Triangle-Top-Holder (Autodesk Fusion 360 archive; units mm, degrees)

design "Triangle-Top-Holder" references "Base"
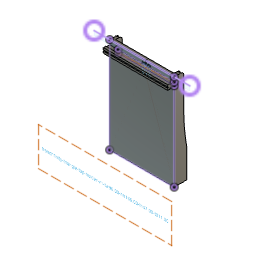
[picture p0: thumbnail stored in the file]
parameter "tool_width" = 96
parameter "holder_height" = 155
parameter "triangle_height" = 47
parameter "tolerance" = 1
parameter "wall_thickness" = 5
parameter "tool_depth" = 11
sketch "Base" plane through (0, 0, 0) normal (0, 1, 0) x axis (1, 0, 0)
  line L1 (108, 0) -> (0, 0)
  line L2 (108, -160) -> (108, 0)
  line L3 (0, -160) -> (108, -160)
  line L4 (0, 0) -> (0, -160)
  line L5 (54, -48) -> (54, 0)
  line L6 (108, -48) -> (54, -48)
  line L7 (103, -155) -> (103, -5)
  line L8 (5, -155) -> (103, -155)
  line L9 (5, -5) -> (5, -155)
  line L10 (103, -5) -> (5, -5)
  line L11 (54, -5) -> (103, -48)
  line L12 (54, -5) -> (5, -48)
  line L13 (103, -160) -> (103, -155)
  line L14 (5, -160) -> (5, -155)
  point P1 (0, 0)
  point P2 (0, 0)
  point P6 (54, 0)
  point P8 (108, -48)
  point P13 (103, -48)
  point P14 (54, -5)
  point P15 (5, -48)
  point P16 (54, -5)
  point P17 (103, -160)
  point P10 (103, -155)
  point P18 (5, -155)
  point P19 (5, -160)
  point P3 (108, 0)
  point P5 (0, -160)
  point P7 (54, -48)
  horizontal L1
  vertical L2
  horizontal L3
  vertical L4
  coincident P1 P2
  midpoint L1 P6
  perpendicular L1 L5
  coincident L2 P8
  perpendicular L2 L6
  coincident L6 P13
  coincident L7 P13
  midpoint L10 P14
  symmetric L5 P13 P15
  symmetric L5 P14 P16
  coincident L3 P17
  perpendicular L3 L13
  symmetric L5 P10 P18
  symmetric L5 P17 P19
  dimension "d7" distance P2 P3 = 108 (= "wall_thickness + wall_thickness + tolerance + tolerance + tool_width")
  dimension "d8" distance P2 P5 = 160 (= "holder_height + wall_thickness")
  dimension "d9" distance P6 P7 = 48 (= "triangle_height + tolerance")
  dimension "d10" = 5 (= "wall_thickness")
extrude "Extrude1" new body sketch "Base" profile of L1 L2 L3 L4 L10 L9 L8 L7 L11 L12 along normal blind 5 (= "wall_thickness") bodies "Holder"
extrude "Extrude2" add sketch "Base" profile of L1 L2 L3 L4 L10 L9 L7 L11 L12 L13 L14 against normal blind 11 (magnitude of "tool_depth * -1")
sketch "Cover" plane through (0, -11, 0) normal (0, -1, 0) x axis (1, 0, 0)
  line L1 (5, 48) -> (54, 5)
  line L2 (5, 160) -> (5, 48)
  line L3 (0, 160) -> (5, 160)
  line L4 (0, 0) -> (0, 160)
  line L5 (108, 0) -> (0, 0)
  line L6 (108, 160) -> (108, 0)
  line L7 (103, 160) -> (108, 160)
  line L8 (103, 48) -> (103, 160)
  line L9 (54, 5) -> (103, 48)
  line L10 (108, 0) -> (0, 0)
  line L11 (108, 48) -> (108, 0)
  line L12 (0, 48) -> (108, 48)
  line L13 (0, 0) -> (0, 48)
  point P7 (108, 0)
  point P12 (108, 0)
  point P6 (0, 0)
  point P11 (0, 0)
  point P14 (0, 48)
  perpendicular L10 L11
  parallel L10 L12
  parallel L11 L13
  coincident P7 P12
  perpendicular L6 L10
  coincident P6 P11
  dimension "d17" distance P11 P14 = 48 (= "triangle_height + tolerance")
extrude "Extrude3" add sketch "Cover" profile of L1 L2 L4 L5 L6 L8 L9 L10 L11 L12 L13 along normal blind 5 (= "wall_thickness")
fillet "Fillet2" radius 310 (= "holder_height * 2")
fillet "Fillet3" radius 2 5 (= "wall_thickness")
fillet "Fillet4" radius 5
component_insert "Component Insert"
sketch "Reference" plane through (0, 55.6118, 0) normal (0, 1, 0) x axis (-1, 0, 0)
  line L1 (0, 52.6059) -> (-160, 52.6059)
  line L2 (0, 60) -> (0, 52.6059)
  line L3 (-160, 60) -> (0, 60)
  line L4 (-160, 52.6059) -> (-160, 60)
  line L5 (-160, 60) -> (0, 60)
move "Move1"
move "Move2"
extrude "Extrude5" add of existing geometry to an object
extrude "Extrude6" cut of existing geometry to an object
sketch "Text" plane through (0, 55.6118, 0) normal (0, -1, 0) x axis (1, 0, 0)
  line L1 (40, 47.1259) -> (134, 47.1259)
  line L2 (26, -100) -> (26, 60)
  line L3 (134, -100) -> (26, -100)
  line L4 (134, 60) -> (134, 52.4859)
  curve K1
  curve K2
  curve K3
  curve K4
  line L5 (40, 52.4859) -> (40, 47.1259)
  line L6 (134, 52.4859) -> (40, 52.4859)
  line L7 (26, 60) -> (134, 60)
  line L8 (134, 47.1259) -> (134, -100)
  point P5 (134, 52.4859)
  point P3 (40, 47.1259)
  coincident P5
  coincident P3
  dimension "d34" Text1-Height = 3
extrude "Extrude7" cut sketch "Text" against normal blind 2
sketch "Filename" plane through (0, 0, 0) normal (0, 1, 0) x axis (1, 0, 0)
  dimension "d37" = 5
extrude "Extrude8" add of existing geometry to an object
named bodies: "Holder"

design "Base"
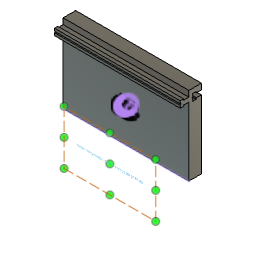
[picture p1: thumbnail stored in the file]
parameter "wall_anchor_height" = 60
parameter "wall_anchor_width" = 20
parameter "wall_anchor_angle" = 45
parameter "width_per_slot" = 40
parameter "slot_inner_width" = 8.5
parameter "slot_inner_height" = 4.5
parameter "slot_outer_width" = 5.6
parameter "slot_outer_height" = 6.5
parameter "slot_dept" = 15
parameter "print_tolerance" = 0.12
parameter "base_plate_thickness" = 16
parameter "base_plate_slot_height" = 50
parameter "wall_anchor_angle_rounded_border" = 1.5
parameter "base_plate_screw_hole_diameter" = 4
parameter "base_plate_screw_head_diameter" = 8
parameter "base_plate_screw_head_height" = 4
parameter "base_plate_screw_hole_side_distance" = 7
parameter "slot_screw_head_width" = 4.42 (= "4.3 mm + print_tolerance")
parameter "slot_screw_thread_width" = 2.12 (= "2 mm + print_tolerance")
parameter "slot_screw_head_height" = 2.12 (= "2 mm + print_tolerance")
parameter "width" = 160
parameter "filament_hole_width" = 1.7
parameter "plate_height" = 80
sketch "Side" plane through (0, 0, 0) normal (1, 0, 0) x axis (0, 1, 0)
  line L1 (39.6118, 0) -> (19.6118, 0)
  line L2 (39.6118, 60) -> (39.6118, 0)
  line L3 (19.6118, 60) -> (39.6118, 60)
  line L4 (19.6118, 0) -> (19.6118, 60)
  line L5 (39.6118, 39.6118) -> (0, 0)
  line L6 (56.0196, 0) -> (0, 0)
  point P1 (0, 0)
  point P6 (0, 0)
  point P7 (39.6118, 39.6118)
  point P2 (19.6118, 0)
  point P3 (39.6118, 0)
  point P5 (19.6118, 60)
  horizontal L1
  vertical L2
  horizontal L3
  vertical L4
  horizontal L6
  coincident P1 P6
  coincident L2 P7
  dimension "d4" distance P2 P3 = 20 (= "wall_anchor_width")
  dimension "d5" distance P2 P5 = 60 (= "wall_anchor_height")
  dimension "d6" angle L5 L6 = 45 (= "wall_anchor_angle")
extrude "Extrude1" new body sketch "Side" profile of L1 L2 L3 L4 L5 along normal blind 40 (= "width_per_slot")
sketch "Slot LeftToRight" plane through (0, 0, 0) normal (-1, 0, 0) x axis (0, -1, 0)
  line L1 (-19.6118, 60) -> (-19.6118, 19.6118)
  line L2 (-39.6118, 60) -> (-19.6118, 60)
  line L3 (-39.6118, 39.6118) -> (-39.6118, 60)
  line L4 (-19.6118, 19.6118) -> (-39.6118, 39.6118)
  line L5 (-39.6118, 52.6059) -> (-39.6118, 49.8059)
  line L6 (-39.6118, 47.0059) -> (-39.6118, 49.8059)
  line L7 (-33.1118, 52.6059) -> (-39.6118, 52.6059)
  line L8 (-28.6118, 49.8059) -> (-39.6118, 49.8059)
  line L9 (-28.6118, 54.0559) -> (-28.6118, 49.8059)
  line L10 (-33.1118, 54.0559) -> (-28.6118, 54.0559)
  line L11 (-33.1118, 52.6059) -> (-33.1118, 54.0559)
  line L12 (-28.6118, 45.5559) -> (-28.6118, 49.8059)
  line L13 (-33.1118, 45.5559) -> (-28.6118, 45.5559)
  line L14 (-33.1118, 47.0059) -> (-33.1118, 45.5559)
  line L15 (-33.1118, 47.0059) -> (-39.6118, 47.0059)
  point P6 (-39.6118, 49.8059)
  point P7 (-39.6118, 52.6059)
  point P17 (-39.6118, 47.0059)
  point P9 (-33.1118, 52.6059)
  point P16 (-33.1118, 47.0059)
  point P10 (-28.6118, 49.8059)
  point P13 (-28.6118, 49.8059)
  point P11 (-28.6118, 54.0559)
  point P14 (-28.6118, 45.5559)
  point P12 (-33.1118, 54.0559)
  point P15 (-33.1118, 45.5559)
  midpoint L3 P6
  parallel L3 L5
  parallel L3 L6
  perpendicular L3 L7
  perpendicular L6 L8
  perpendicular L8 L9
  perpendicular L9 L10
  symmetric P7 L8 P17
  symmetric P9 L8 P16
  symmetric P10 L8 P13
  symmetric L8 P11 P14
  symmetric L8 P12 P15
  dimension "d80" distance P6 P7 = 2.8 (= "slot_outer_width / 2")
  dimension "d82" distance P7 P9 = 6.5 (= "slot_outer_height")
  dimension "d84" distance P6 P10 = 11 (= "slot_outer_height + slot_inner_height")
  dimension "d85" distance P10 P11 = 4.25 (= "slot_inner_width / 2")
  dimension "d86" distance P11 P12 = 4.5 (= "slot_inner_height")
extrude "Extrude3" cut sketch "Slot LeftToRight" profile of L3 L5 L6 L7 L9 L10 L11 L12 L13 L14 L15 against normal blind 40 (magnitude of "width_per_slot * -1")
sketch "Plate" plane through (0, 39.6118, 0) normal (0, 1, 0) x axis (-1, 0, 0)
  line L1 (0, 39.6118) -> (-40, 39.6118)
  line L2 (-40, 60) -> (0, 60)
  line L3 (0, 10) -> (0, 60)
  line L4 (-40, 10) -> (-40, 60)
  line L5 (-40, 10) -> (0, 10)
  line L6 (-40, 47.0059) -> (0, 47.0059)
  line L7 (-40, 52.6059) -> (-40, 60)
  line L8 (0, 60) -> (0, 52.6059)
  line L9 (0, 52.6059) -> (-40, 52.6059)
  line L10 (-40, 60) -> (0, 60)
  line L11 (-40, 39.6118) -> (-40, 47.0059)
  line L12 (0, 47.0059) -> (0, 39.6118)
  point P2 (0, 60)
  point P3 (-40, 60)
  point P4 (0, 10)
  point P5 (-40, 10)
  perpendicular L1 L3
  perpendicular L1 L4
  dimension "d36" distance P2 P3 = 40 (= "width_per_slot")
  dimension "d37" distance P2 P4 = 50 (= "base_plate_slot_height")
  dimension "d39" distance P3 P5 = 50 (= "base_plate_slot_height")
extrude "Extrude6" new body sketch "Plate" profile of L1 L2 L3 L4 L5 L6 L7 L8 L9 L10 along normal blind 16 (= "base_plate_thickness") bodies "Base plate with slot"
sketch "Slot" plane through (0, 0, 0) normal (-1, 0, 0) x axis (0, -1, 0)
  line L1 (-19.6118, 60) -> (-19.6118, 19.6118)
  line L2 (-39.6118, 60) -> (-19.6118, 60)
  line L3 (-39.6118, 52.6059) -> (-39.6118, 60)
  line L4 (-33.1118, 52.6059) -> (-39.6118, 52.6059)
  line L5 (-33.1118, 54.0559) -> (-33.1118, 52.6059)
  line L6 (-28.6118, 54.0559) -> (-33.1118, 54.0559)
  line L7 (-28.6118, 45.5559) -> (-28.6118, 54.0559)
  line L8 (-33.1118, 45.5559) -> (-28.6118, 45.5559)
  line L9 (-33.1118, 47.0059) -> (-33.1118, 45.5559)
  line L10 (-39.6118, 47.0059) -> (-33.1118, 47.0059)
  line L11 (-39.6118, 39.6118) -> (-39.6118, 47.0059)
  line L12 (-19.6118, 19.6118) -> (-39.6118, 39.6118)
  line L13 (-33.1118, 52.6059) -> (-39.6118, 52.6059)
  line L14 (-33.1118, 54.0559) -> (-33.1118, 52.6059)
  line L15 (-28.6118, 54.0559) -> (-33.1118, 54.0559)
  line L16 (-28.6118, 45.5559) -> (-28.6118, 54.0559)
  line L17 (-33.1118, 45.5559) -> (-28.6118, 45.5559)
  line L18 (-33.1118, 47.0059) -> (-33.1118, 45.5559)
  line L19 (-39.6118, 47.0059) -> (-33.1118, 47.0059)
  line L20 (-39.6118, 10) -> (-39.6118, 60)
  line L21 (-32.9918, 52.4859) -> (-39.6118, 52.4859)
  line L22 (-32.9918, 53.9359) -> (-32.9918, 52.4859)
  line L23 (-28.7318, 53.9359) -> (-32.9918, 53.9359)
  line L24 (-28.7318, 45.6759) -> (-28.7318, 53.9359)
  line L25 (-32.9918, 45.6759) -> (-28.7318, 45.6759)
  line L26 (-32.9918, 47.1259) -> (-32.9918, 45.6759)
  line L27 (-39.6118, 47.1259) -> (-32.9918, 47.1259)
  line L28 (-33.1118, 52.6059) -> (-39.6118, 52.6059)
  line L29 (-33.1118, 52.6059) -> (-33.1118, 54.0559)
  line L30 (-28.6118, 54.0559) -> (-33.1118, 54.0559)
  line L31 (-28.6118, 45.5559) -> (-28.6118, 54.0559)
  line L32 (-33.1118, 45.5559) -> (-28.6118, 45.5559)
  line L33 (-33.1118, 47.0059) -> (-33.1118, 45.5559)
  line L34 (-39.6118, 47.0059) -> (-33.1118, 47.0059)
  line L35 (-39.6118, 47.0059) -> (-39.6118, 52.6059)
  line L36 (-49.1118, 52.6059) -> (-55.6118, 52.6059)
  line L37 (-49.1118, 52.6059) -> (-49.1118, 54.0559)
  line L38 (-44.6118, 54.0559) -> (-49.1118, 54.0559)
  line L39 (-44.6118, 45.5559) -> (-44.6118, 54.0559)
  line L40 (-49.1118, 45.5559) -> (-44.6118, 45.5559)
  line L41 (-49.1118, 47.0059) -> (-49.1118, 45.5559)
  line L42 (-55.6118, 47.0059) -> (-49.1118, 47.0059)
  line L43 (-55.6118, 47.0059) -> (-55.6118, 52.6059)
  point P15 (-39.6118, 52.6059)
  point P33 (-39.6118, 52.6059)
  point P16 (-33.1118, 52.6059)
  point P34 (-33.1118, 52.6059)
  point P17 (-33.1118, 54.0559)
  point P35 (-33.1118, 54.0559)
  point P36 (-33.1118, 52.6059)
  point P18 (-28.6118, 54.0559)
  point P37 (-28.6118, 54.0559)
  point P19 (-28.6118, 45.5559)
  point P38 (-28.6118, 45.5559)
  point P10 (-28.6118, 45.5559)
  point P39 (-28.6118, 45.5559)
  point P11 (-33.1118, 45.5559)
  point P40 (-33.1118, 45.5559)
  point P41 (-33.1118, 45.5559)
  point P12 (-33.1118, 47.0059)
  point P42 (-33.1118, 47.0059)
  point P21 (-33.1118, 47.0059)
  point P43 (-33.1118, 47.0059)
  point P22 (-39.6118, 47.0059)
  point P44 (-39.6118, 47.0059)
  point P45 (-39.6118, 52.6059)
  point P46 (-39.6118, 47.0059)
  coincident P15 P33
  coincident P16 P34
  coincident P17 P35
  coincident P16 P36
  coincident P18 P37
  coincident P19 P38
  coincident P10 P39
  coincident P11 P40
  coincident P11 P41
  coincident P12 P42
  coincident P21 P43
  coincident P22 P44
  coincident P15 P45
  coincident P22 P46
  dimension "d91" = 0.12 (= "print_tolerance")
  dimension "d96" R-Pattern1-uDistance = -16 (= "base_plate_thickness * -1")
  dimension "d97" R-Pattern1-vDistance = 0
extrude "Extrude7" add sketch "Slot" profile of L20 L24 L23 L27 L22 L25 L26 L21 against normal blind 40 (magnitude of "width_per_slot * -1")
extrude "Extrude8" cut sketch "Slot" profile of L36 L37 L38 L39 L40 L41 L42 L43 no distance stored
sketch "Sketch3" plane through (0, 0, 0) normal (-1, 0, 0) x axis (0, -1, 0)
  line L1 (-32.9918, 47.1259) -> (-39.6118, 47.1259)
  line L2 (-32.9918, 45.6759) -> (-32.9918, 47.1259)
  line L3 (-28.7318, 45.6759) -> (-32.9918, 45.6759)
  line L4 (-28.7318, 53.9359) -> (-28.7318, 45.6759)
  line L5 (-32.9918, 53.9359) -> (-28.7318, 53.9359)
  line L6 (-32.9918, 52.4859) -> (-32.9918, 53.9359)
  line L7 (-39.6118, 52.4859) -> (-32.9918, 52.4859)
  line L8 (-44.6118, 45.5559) -> (-44.6118, 54.0559)
  line L9 (-32.9918, 52.4859) -> (-39.6118, 52.4859)
  line L10 (-32.9918, 53.9359) -> (-32.9918, 52.4859)
  line L11 (-28.7318, 53.9359) -> (-32.9918, 53.9359)
  line L12 (-28.7318, 45.6759) -> (-28.7318, 53.9359)
  line L13 (-32.9918, 45.6759) -> (-28.7318, 45.6759)
  line L14 (-32.9918, 47.1259) -> (-32.9918, 45.6759)
  line L15 (-39.6118, 47.1259) -> (-32.9918, 47.1259)
  line L16 (-39.6118, 47.1259) -> (-39.6118, 52.4859)
  line L17 (-55.6118, 52.4859) -> (-48.9918, 52.4859)
  line L18 (-48.9918, 52.4859) -> (-48.9918, 53.9359)
  line L19 (-48.9918, 53.9359) -> (-44.7318, 53.9359)
  line L20 (-44.7318, 45.6759) -> (-44.7318, 53.9359)
  line L21 (-48.9918, 45.6759) -> (-44.7318, 45.6759)
  line L22 (-48.9918, 47.1259) -> (-48.9918, 45.6759)
  line L23 (-55.6118, 47.1259) -> (-48.9918, 47.1259)
  line L24 (-55.6118, 47.1259) -> (-55.6118, 52.4859)
  line L25 (-55.6118, 47.0059) -> (-49.1118, 47.0059)
  line L26 (-55.6118, 10) -> (-55.6118, 47.0059)
  line L27 (-39.6118, 10) -> (-55.6118, 10)
  line L28 (-39.6118, 47.1259) -> (-39.6118, 10)
  line L29 (-39.6118, 60) -> (-39.6118, 52.4859)
  line L30 (-55.6118, 60) -> (-39.6118, 60)
  line L31 (-55.6118, 52.6059) -> (-55.6118, 60)
  line L32 (-49.1118, 52.6059) -> (-55.6118, 52.6059)
  line L33 (-49.1118, 54.0559) -> (-49.1118, 52.6059)
  line L34 (-44.6118, 54.0559) -> (-49.1118, 54.0559)
  line L35 (-49.1118, 45.5559) -> (-44.6118, 45.5559)
  line L36 (-49.1118, 47.0059) -> (-49.1118, 45.5559)
  point P9 (-39.6118, 52.4859)
  point P20 (-39.6118, 52.4859)
  point P19 (-39.6118, 47.1259)
  point P21 (-39.6118, 47.1259)
  coincident P9 P20
  coincident P19 P21
  dimension "d105" R-Pattern1-vDistance = 0
extrude "Extrude3" new body sketch "Sketch3" profile of L17 L18 L19 L20 L21 L22 L23 L24 against normal blind 40 (magnitude of "width_per_slot * -1")
sketch "Screw hole" plane through (0, 28.6118, 0) normal (0, 1, 0) x axis (-1, 0, 0)
  line L1 (0, 54.0559) -> (0, 45.5559)
  line L2 (-40, 54.0559) -> (0, 54.0559)
  line L3 (-40, 45.5559) -> (-40, 54.0559)
  line L4 (0, 45.5559) -> (-40, 45.5559)
  line L5 (0, 45.5559) -> (-40, 54.0559)
  line L6 (-40, 45.5559) -> (0, 54.0559)
  circle C1 centre (-20, 49.8059) radius 2.21
  circle C2 centre (-20, 49.8059) radius 1.06
  point P4 (-40, 54.0559)
  point P6 (-40, 54.0559)
  point P2 (0, 45.5559)
  point P7 (0, 45.5559)
  point P3 (0, 54.0559)
  point P8 (0, 54.0559)
  point P5 (-40, 45.5559)
  point P9 (-40, 45.5559)
  point P10 (-20, 49.8059)
  coincident P4 P6
  coincident P2 P7
  coincident P3 P8
  coincident P5 P9
  midpoint L5 P10
  concentric C1 C2
  dimension "d119" diameter C1 = 4.42 (= "slot_screw_head_width")
  dimension "d120" diameter C2 = 2.12 (= "slot_screw_thread_width")
extrude "Extrude4" cut sketch "Screw hole" profile of C2 against normal blind 2000
extrude "Extrude5" cut sketch "Screw hole" profile of C1 C2 no distance stored
fillet "Fillet1" radius 1.5 (= "wall_anchor_angle_rounded_border")
work_plane "WorkPlane1" sketch "Slot LeftToRight" AlongDistance -20 (= "-width_per_slot / 2")
sketch "Screw head" plane through (20, 0, 0) normal (-1, 0, 0) x axis (0, -1, 0)
  line L1 (-28.6118, 52.0159) -> (-28.6118, 47.5959)
  line L2 (-26.4918, 52.0159) -> (-26.4918, 47.5959)
  line L3 (-26.4918, 48.7459) -> (-26.4918, 50.8659)
  line L4 (-26.4918, 50.8659) -> (-28.6118, 52.0159)
  line L5 (-26.4918, 52.0159) -> (-28.6118, 52.0159)
  point P3 (-28.6118, 52.0159)
  point P8 (-28.6118, 52.0159)
  point P6 (-26.4918, 50.8659)
  point P9 (-26.4918, 50.8659)
  point P10 (-28.6118, 52.0159)
  point P5 (-26.4918, 52.0159)
  point P11 (-26.4918, 52.0159)
  coincident P3 P8
  coincident P6 P9
  coincident P3 P10
  coincident P5 P11
revolve "Revolve1" sketch "Screw head" AlongAngle 360
sketch "Plate" plane through (0, 39.6118, 0) normal (0, 1, 0) x axis (-1, 0, 0)
  line L1 (0, 39.6118) -> (-40, 39.6118)
  line L2 (-40, 60) -> (0, 60)
  line L3 (0, 10) -> (0, 60)
  line L4 (-40, 10) -> (-40, 60)
  line L5 (-40, 10) -> (0, 10)
  line L6 (-40, 47.0059) -> (0, 47.0059)
  line L7 (-40, 39.6118) -> (-40, 47.0059)
  line L8 (0, 47.0059) -> (0, 39.6118)
  line L9 (0, 52.6059) -> (-40, 52.6059)
  line L10 (-40, 60) -> (0, 60)
  line L11 (0, 60) -> (0, 52.6059)
  line L12 (-40, 52.6059) -> (-40, 60)
  point P2 (0, 60)
  point P3 (-40, 60)
  point P4 (0, 10)
  point P5 (-40, 10)
  perpendicular L1 L3
  perpendicular L1 L4
  dimension "d36_1" distance P2 P3 = 40 (= "width_per_slot")
  dimension "d37_1" distance P2 P4 = 50 (= "base_plate_slot_height")
  dimension "d39_1" distance P3 P5 = 50 (= "base_plate_slot_height")
extrude "Extrude6" new body sketch "Plate" profile of L1 L2 L3 L4 L5 L6 L7 L8 L9 L10 along normal blind 16 (= "base_plate_thickness") named "d89_1" bodies "Base plate with slot"
sketch "Slot" plane through (0, 0, 0) normal (-1, 0, 0) x axis (0, -1, 0)
  line L1 (-19.6118, 60) -> (-19.6118, 23.2332)
  line L2 (-39.6118, 60) -> (-19.6118, 60)
  line L3 (-39.6118, 52.6059) -> (-39.6118, 60)
  line L4 (-33.1118, 52.6059) -> (-39.6118, 52.6059)
  line L5 (-33.1118, 54.0559) -> (-33.1118, 52.6059)
  line L6 (-28.6118, 54.0559) -> (-33.1118, 54.0559)
  line L7 (-28.6118, 45.5559) -> (-28.6118, 54.0559)
  line L8 (-33.1118, 45.5559) -> (-28.6118, 45.5559)
  line L9 (-33.1118, 47.0059) -> (-33.1118, 45.5559)
  line L10 (-39.6118, 47.0059) -> (-33.1118, 47.0059)
  line L11 (-39.6118, 39.6118) -> (-39.6118, 47.0059)
  line L12 (-22.1725, 22.1725) -> (-39.6118, 39.6118)
  line L13 (-33.1118, 52.6059) -> (-39.6118, 52.6059)
  line L14 (-33.1118, 54.0559) -> (-33.1118, 52.6059)
  line L15 (-28.6118, 54.0559) -> (-33.1118, 54.0559)
  line L16 (-28.6118, 45.5559) -> (-28.6118, 54.0559)
  line L17 (-33.1118, 45.5559) -> (-28.6118, 45.5559)
  line L18 (-33.1118, 47.0059) -> (-33.1118, 45.5559)
  line L19 (-39.6118, 47.0059) -> (-33.1118, 47.0059)
  line L20 (-39.6118, 10) -> (-39.6118, 60)
  line L21 (-32.9918, 52.4859) -> (-39.6118, 52.4859)
  line L22 (-32.9918, 53.9359) -> (-32.9918, 52.4859)
  line L23 (-28.7318, 53.9359) -> (-32.9918, 53.9359)
  line L24 (-28.7318, 45.6759) -> (-28.7318, 53.9359)
  line L25 (-32.9918, 45.6759) -> (-28.7318, 45.6759)
  line L26 (-32.9918, 47.1259) -> (-32.9918, 45.6759)
  line L27 (-39.6118, 47.1259) -> (-32.9918, 47.1259)
  line L28 (-33.1118, 52.6059) -> (-39.6118, 52.6059)
  line L29 (-33.1118, 52.6059) -> (-33.1118, 54.0559)
  line L30 (-28.6118, 54.0559) -> (-33.1118, 54.0559)
  line L31 (-28.6118, 45.5559) -> (-28.6118, 54.0559)
  line L32 (-33.1118, 45.5559) -> (-28.6118, 45.5559)
  line L33 (-33.1118, 47.0059) -> (-33.1118, 45.5559)
  line L34 (-39.6118, 47.0059) -> (-33.1118, 47.0059)
  line L35 (-39.6118, 47.0059) -> (-39.6118, 52.6059)
  line L36 (-49.1118, 52.6059) -> (-55.6118, 52.6059)
  line L37 (-49.1118, 52.6059) -> (-49.1118, 54.0559)
  line L38 (-44.6118, 54.0559) -> (-49.1118, 54.0559)
  line L39 (-44.6118, 45.5559) -> (-44.6118, 54.0559)
  line L40 (-49.1118, 45.5559) -> (-44.6118, 45.5559)
  line L41 (-49.1118, 47.0059) -> (-49.1118, 45.5559)
  line L42 (-55.6118, 47.0059) -> (-49.1118, 47.0059)
  line L43 (-55.6118, 47.0059) -> (-55.6118, 52.6059)
  arc A1 centre (-21.1118, 23.2332) radius 1.5 clockwise from (-19.6118, 23.2332) to (-22.1725, 22.1725)
  point P15 (-39.6118, 52.6059)
  point P33 (-39.6118, 52.6059)
  point P16 (-33.1118, 52.6059)
  point P34 (-33.1118, 52.6059)
  point P17 (-33.1118, 54.0559)
  point P35 (-33.1118, 54.0559)
  point P36 (-33.1118, 52.6059)
  point P18 (-28.6118, 54.0559)
  point P37 (-28.6118, 54.0559)
  point P19 (-28.6118, 45.5559)
  point P38 (-28.6118, 45.5559)
  point P10 (-28.6118, 45.5559)
  point P39 (-28.6118, 45.5559)
  point P11 (-33.1118, 45.5559)
  point P40 (-33.1118, 45.5559)
  point P41 (-33.1118, 45.5559)
  point P12 (-33.1118, 47.0059)
  point P42 (-33.1118, 47.0059)
  point P21 (-33.1118, 47.0059)
  point P43 (-33.1118, 47.0059)
  point P22 (-39.6118, 47.0059)
  point P44 (-39.6118, 47.0059)
  point P45 (-39.6118, 52.6059)
  point P46 (-39.6118, 47.0059)
  coincident P15 P33
  coincident P16 P34
  coincident P17 P35
  coincident P16 P36
  coincident P18 P37
  coincident P19 P38
  coincident P10 P39
  coincident P11 P40
  coincident P11 P41
  coincident P12 P42
  coincident P21 P43
  coincident P22 P44
  coincident P15 P45
  coincident P22 P46
  dimension "d91_1" = 0.12 (= "print_tolerance")
  dimension "d96_1" R-Pattern1-uDistance = -16 (= "base_plate_thickness * -1")
  dimension "d97_1" R-Pattern1-vDistance = 0
extrude "Extrude8" cut sketch "Slot" profile of L36 L37 L38 L39 L40 L41 L42 L43 no distance stored
sketch "Screw" plane through (0, 55.6118, 0) normal (0, 1, 0) x axis (-1, 0, 0)
  line L1 (-40, 47.0059) -> (0, 47.0059)
  line L2 (-40, 10) -> (-40, 47.0059)
  line L3 (0, 10) -> (-40, 10)
  line L4 (0, 47.0059) -> (0, 10)
  line L5 (-33, 17) -> (-33, 40.0059)
  line L6 (-7, 17) -> (-33, 17)
  line L7 (-7, 40.0059) -> (-7, 17)
  line L8 (-33, 40.0059) -> (-7, 40.0059)
  circle C1 centre (-33, 17) radius 4
  circle C2 centre (-33, 17) radius 2
  point P7 (-33, 17)
  point P10 (-33, 17)
  coincident P7 P10
  concentric C1 C2
  dimension "d127" = -7 (= "base_plate_screw_hole_side_distance * -1")
  dimension "d128" diameter C1 = 8
  dimension "d129" diameter C2 = 4
rectangular_pattern "R-Pattern2" countU 4 (= "floor(( width / mm ) / ( width_per_slot / cm * 10 ))") uSpaceDistance 40 (= "width_per_slot") vSpaceDistance 0 bodies "Wall anchor part (1)", "Wall anchor part (2)", "Wall anchor part (3)"
work_plane "WorkPlane2"
extrude "Extrude12" new body of existing geometry no distance stored
mirror "Mirror3" mirrorStitchTolerance 0.1
sketch "filename" plane through (0, 19.6118, 0) normal (0, -1, 0) x axis (1, 0, 0)
  dimension "d216" = 3
sketch "Text" plane through (0, 19.6118, 0) normal (0, -1, 0) x axis (1, 0, 0)
  line L1 (179.5, 60) -> (179.5, 23.2332)
  line L2 (160, 23.2332) -> (160, 60)
  line L3 (179.5, 23.2332) -> (160, 23.2332)
  line L4 (179.5, 60) -> (179.5, 23.2332)
  line L5 (160, 60) -> (179.5, 60)
  line L6 (0, 60) -> (0, 23.2332)
  line L7 (-19.5, 60) -> (0, 60)
  line L8 (-19.5, 23.2332) -> (-19.5, 60)
  line L9 (0, 23.2332) -> (-19.5, 23.2332)
  curve K1
  curve K2
  curve K3
  curve K4
  line L10 (80, 60) -> (40, 60)
  point P4 (179.5, 23.2332)
  point P2 (-19.5, 60)
  coincident P4
  coincident P2
  parallel K3 L10
  dimension "d229" Text1-Height = 3
extrude "Extrude19" cut sketch "Text" against normal blind 2
extrude "Extrude14" cut of existing geometry blind 60 (= "( width_per_slot - width ) / -2")
extrude "Extrude15" cut of existing geometry blind 60 (= "( width_per_slot - width ) / -2")
extrude "Extrude9" cut of existing geometry blind -39 (= "-width_per_slot + 1 mm")
extrude "Extrude10" add of existing geometry blind 159 (= "width - 1 mm")
extrude "Extrude13" cut of existing geometry blind -30
extrude "Extrude14" add of existing geometry blind 80 (= "plate_height")
sketch "Sketch7" plane through (0, 39.6118, 0) normal (0, -1, 0) x axis (1, 0, 0)
  dimension "d236" = 3
extrude "Extrude11" cut sketch "Sketch7" against normal blind 2
sketch "File name" plane through (0, 39.6118, 0) normal (0, -1, 0) x axis (1, 0, 0)
  line L1 (72.897, 7.4163) -> (72.6596, 7.4163)
  line L2 (72.897, 4.404) -> (72.897, 7.4163)
  line L3 (72.5287, 4.404) -> (72.897, 4.404)
  line L4 (72.5287, 6.7512) -> (72.5287, 4.404)
  curve K1 (72.1787, 6.4975) -> (72.5287, 6.7512)
  curve K2 (71.792, 6.3072) -> (72.1787, 6.4975)
  line L5 (71.792, 6.6632) -> (71.792, 6.3072)
  curve K3 (72.3322, 7.0152) -> (71.792, 6.6632)
  curve K4 (72.6596, 7.4163) -> (72.3322, 7.0152)
  line L6 (76.1242, 4.404) -> (76.5641, 6.0759)
  line L7 (75.7394, 4.404) -> (76.1242, 4.404)
  line L8 (75.0744, 6.5773) -> (75.7394, 4.404)
  line L9 (75.455, 6.5773) -> (75.0744, 6.5773)
  line L10 (75.8008, 5.3229) -> (75.455, 6.5773)
  line L11 (75.9297, 4.8563) -> (75.8008, 5.3229)
  curve K5 (76.0423, 5.3044) -> (75.9297, 4.8563)
  line L12 (76.3881, 6.5773) -> (76.0423, 5.3044)
  line L13 (76.7667, 6.5773) -> (76.3881, 6.5773)
  line L14 (77.0921, 5.3167) -> (76.7667, 6.5773)
  line L15 (77.2006, 4.9013) -> (77.0921, 5.3167)
  line L16 (77.3254, 5.3208) -> (77.2006, 4.9013)
  line L17 (77.6978, 6.5773) -> (77.3254, 5.3208)
  line L18 (78.0559, 6.5773) -> (77.6978, 6.5773)
  line L19 (77.3765, 4.404) -> (78.0559, 6.5773)
  line L20 (76.9939, 4.404) -> (77.3765, 4.404)
  line L21 (76.648, 5.7055) -> (76.9939, 4.404)
  line L22 (76.5641, 6.0759) -> (76.648, 5.7055)
  line L23 (74.9311, 5.3044) -> (74.9311, 5.6748)
  line L24 (73.7995, 5.3044) -> (74.9311, 5.3044)
  line L25 (73.7995, 5.6748) -> (73.7995, 5.3044)
  line L26 (74.9311, 5.6748) -> (73.7995, 5.6748)
  line L27 (70.4638, 4.404) -> (71.2865, 6.5773)
  line L28 (70.1201, 4.404) -> (70.4638, 4.404)
  line L29 (69.2933, 6.5773) -> (70.1201, 4.404)
  line L30 (69.6821, 6.5773) -> (69.2933, 6.5773)
  line L31 (70.1487, 5.2758) -> (69.6821, 6.5773)
  curve K6 (70.2879, 4.8379) -> (70.1487, 5.2758)
  curve K7 (70.425, 5.2512) -> (70.2879, 4.8379)
  line L32 (70.9079, 6.5773) -> (70.425, 5.2512)
  line L33 (71.2865, 6.5773) -> (70.9079, 6.5773)
  line L34 (0, 47.1259) -> (160, 47.1259)
  line L35 (0, -40) -> (0, 47.1259)
  line L36 (160, 47.1259) -> (160, -40)
  curve K8
  curve K9
  curve K10
  curve K11
  line L37 (160, -40) -> (0, -40)
  curve K12 (78.545, 6.3072) -> (78.9318, 6.4975)
  curve K13 (79.0853, 7.0152) -> (78.545, 6.6632)
  curve K14 (77.4512, 1.9606) -> (77.5617, 1.5882)
  curve K15 (80.9434, 5.9511) -> (81.0478, 6.6448)
  curve K16 (81.2688, 6.2519) -> (80.9434, 5.9511)
  curve K17 (78.9318, 6.4975) -> (79.2817, 6.7512)
  curve K18 (79.4127, 7.4163) -> (79.0853, 7.0152)
  curve K19 (81.322, 7.0152) -> (81.631, 7.1134)
  curve K20 (81.0478, 6.6448) -> (81.322, 7.0152)
  curve K21 (77.5617, 1.5882) -> (77.9014, 1.3488)
  line L38 (79.2817, 4.404) -> (79.6501, 4.404)
  curve K22 (75.4744, 0.9108) -> (75.5358, 1.3119)
  curve K23 (81.6719, 6.3501) -> (81.2688, 6.2519)
  curve K24 (81.9993, 6.9559) -> (82.1385, 6.6407)
  curve K25 (83.0327, 6.7389) -> (82.9243, 5.8836)
  curve K26 (83.3581, 7.2403) -> (83.0327, 6.7389)
  curve K27 (78.9451, 2.505) -> (78.3128, 2.7342)
  curve K28 (79.1845, 1.9504) -> (78.9451, 2.505)
  curve K29 (79.074, 1.5862) -> (79.1845, 1.9504)
  curve K30 (81.631, 7.1134) -> (81.9993, 6.9559)
  curve K31 (86.4195, 5.8836) -> (86.7162, 4.6639)
  curve K32 (83.1606, 1.2014) -> (83.4574, -0.0182)
  curve K33 (76.3871, 1.5002) -> (76.5078, 1.0991)
  line L39 (82.1385, 6.6407) -> (82.5048, 6.6694)
  curve K34 (80.8984, 7.0725) -> (80.5771, 5.8078)
  curve K35 (82.2326, 7.2178) -> (81.6535, 7.4163)
  curve K36 (82.5048, 6.6694) -> (82.2326, 7.2178)
  curve K37 (88.1221, 7.0377) -> (87.8213, 7.3181)
  curve K38 (88.3083, 6.5916) -> (88.1221, 7.0377)
  curve K39 (88.3759, 5.8836) -> (88.3083, 6.5916)
  curve K40 (88.2674, 5.0302) -> (88.3759, 5.8836)
  curve K41 (87.942, 4.5289) -> (88.2674, 5.0302)
  curve K42 (87.3977, 4.3529) -> (87.942, 4.5289)
  curve K43 (86.7162, 4.6639) -> (87.3977, 4.3529)
  curve K44 (74.662, 0.8249) -> (74.5536, 1.3958)
  curve K45 (74.5413, 0.2233) -> (74.662, 0.8249)
  curve K46 (74.1934, -0.186) -> (74.5413, 0.2233)
  curve K47 (73.7145, -0.3272) -> (74.1934, -0.186)
  curve K48 (73.383, -0.2495) -> (73.7145, -0.3272)
  curve K49 (73.1436, -0.053) -> (73.383, -0.2495)
  curve K50 (78.7425, 1.3488) -> (79.074, 1.5862)
  curve K51 (79.162, 1.0582) -> (78.7425, 1.3488)
  curve K52 (79.3073, 0.5793) -> (79.162, 1.0582)
  curve K53 (79.0351, -0.0673) -> (79.3073, 0.5793)
  curve K54 (78.3189, -0.3293) -> (79.0351, -0.0673)
  curve K55 (77.6027, -0.0673) -> (78.3189, -0.3293)
  curve K56 (77.3305, 0.5896) -> (77.6027, -0.0673)
  curve K57 (77.4778, 1.0786) -> (77.3305, 0.5896)
  curve K58 (77.9014, 1.3488) -> (77.4778, 1.0786)
  curve K59 (84.8632, 2.3556) -> (84.5624, 2.6359)
  curve K60 (85.0495, 1.9095) -> (84.8632, 2.3556)
  curve K61 (85.117, 1.2014) -> (85.0495, 1.9095)
  curve K62 (85.0085, 0.3481) -> (85.117, 1.2014)
  curve K63 (84.6832, -0.1533) -> (85.0085, 0.3481)
  curve K64 (84.1388, -0.3293) -> (84.6832, -0.1533)
  curve K65 (83.4574, -0.0182) -> (84.1388, -0.3293)
  curve K66 (81.368, 2.3556) -> (81.0672, 2.6359)
  curve K67 (81.5542, 1.9095) -> (81.368, 2.3556)
  curve K68 (81.6218, 1.2014) -> (81.5542, 1.9095)
  curve K69 (81.5133, 0.3481) -> (81.6218, 1.2014)
  curve K70 (81.1879, -0.1533) -> (81.5133, 0.3481)
  curve K71 (80.6436, -0.3293) -> (81.1879, -0.1533)
  curve K72 (79.9621, -0.0182) -> (80.6436, -0.3293)
  curve K73 (79.6654, 1.2014) -> (79.9621, -0.0182)
  curve K74 (90.4529, 7.0377) -> (90.1521, 7.3181)
  curve K75 (90.6392, 6.5916) -> (90.4529, 7.0377)
  curve K76 (90.7067, 5.8836) -> (90.6392, 6.5916)
  curve K77 (90.5982, 5.0302) -> (90.7067, 5.8836)
  curve K78 (90.2729, 4.5289) -> (90.5982, 5.0302)
  curve K79 (89.7285, 4.3529) -> (90.2729, 4.5289)
  curve K80 (89.0471, 4.6639) -> (89.7285, 4.3529)
  curve K81 (88.7503, 5.8836) -> (89.0471, 4.6639)
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  dimension "d239" Text1-Height = 3
sketch "Sketch4" plane through (40, 0, 0) normal (1, 0, 0) x axis (0, 1, 0)
  line L1 (44.7318, 53.9359) -> (48.9918, 53.9359)
  line L2 (44.7318, 45.6759) -> (44.7318, 53.9359)
  line L3 (48.9918, 45.6759) -> (44.7318, 45.6759)
  line L4 (48.9918, 47.1259) -> (48.9918, 45.6759)
  line L5 (55.6118, 47.1259) -> (48.9918, 47.1259)
  line L6 (55.6118, 52.4859) -> (55.6118, 47.1259)
  line L7 (48.9918, 52.4859) -> (55.6118, 52.4859)
  line L8 (48.9918, 53.9359) -> (48.9918, 52.4859)
  circle C1 centre (44.7318, 49.8059) radius 0.85
  point P10 (44.7318, 49.8059)
  midpoint L2 P10
  dimension "d241" diameter C1 = 1.7 (= "filament_hole_width")
extrude "Extrude4" cut sketch "Sketch4" profile of L2 C1 no distance stored
sketch "Sketch15" plane through (-19.5, 0, 0) normal (-1, 0, 0) x axis (0, -1, 0)
  line L1 (-19.6118, 60) -> (-19.6118, 23.2332)
  line L2 (-39.6118, 60) -> (-19.6118, 60)
  line L3 (-39.6118, 52.6059) -> (-39.6118, 60)
  line L4 (-33.1118, 52.6059) -> (-39.6118, 52.6059)
  line L5 (-33.1118, 54.0559) -> (-33.1118, 52.6059)
  line L6 (-28.6118, 54.0559) -> (-33.1118, 54.0559)
  line L7 (-28.6118, 45.5559) -> (-28.6118, 54.0559)
  line L8 (-33.1118, 45.5559) -> (-28.6118, 45.5559)
  line L9 (-33.1118, 47.0059) -> (-33.1118, 45.5559)
  line L10 (-39.6118, 47.0059) -> (-33.1118, 47.0059)
  line L11 (-39.6118, 39.6118) -> (-39.6118, 47.0059)
  line L12 (-22.1725, 22.1725) -> (-39.6118, 39.6118)
  arc A1 centre (-21.1118, 23.2332) radius 1.5 clockwise from (-19.6118, 23.2332) to (-22.1725, 22.1725)
  circle C1 centre (-28.6118, 49.8059) radius 0.85
  point P16 (-28.6118, 49.8059)
  midpoint L7 P16
  dimension "d244" diameter C1 = 1.7 (= "filament_hole_width")
sketch "Sketch9" plane through (160, 0, 0) normal (1, 0, 0) x axis (0, 1, 0)
  line L1 (49.1118, 47.0059) -> (55.6118, 47.0059)
  line L2 (49.1118, 45.5559) -> (49.1118, 47.0059)
  line L3 (44.6118, 45.5559) -> (49.1118, 45.5559)
  line L4 (44.6118, 54.0559) -> (44.6118, 45.5559)
  line L5 (49.1118, 54.0559) -> (44.6118, 54.0559)
  line L6 (49.1118, 52.6059) -> (49.1118, 54.0559)
  line L7 (55.6118, 52.6059) -> (49.1118, 52.6059)
  line L8 (55.6118, 47.0059) -> (55.6118, -40)
  line L9 (39.6118, 60) -> (55.6118, 60)
  line L10 (39.6118, 52.4859) -> (39.6118, 60)
  line L11 (32.9918, 52.4859) -> (39.6118, 52.4859)
  line L12 (32.9918, 53.9359) -> (32.9918, 52.4859)
  line L13 (28.7318, 53.9359) -> (32.9918, 53.9359)
  line L14 (28.7318, 45.6759) -> (28.7318, 53.9359)
  line L15 (32.9918, 45.6759) -> (28.7318, 45.6759)
  line L16 (32.9918, 47.1259) -> (32.9918, 45.6759)
  line L17 (39.6118, 47.1259) -> (32.9918, 47.1259)
  line L18 (55.6118, 60) -> (55.6118, 52.6059)
  line L19 (39.6118, -40) -> (39.6118, 47.1259)
  line L20 (55.6118, -40) -> (39.6118, -40)
  circle C1 centre (28.7318, 49.8059) radius 0.85
  circle C2 centre (44.6118, 49.8059) radius 0.85
  point P20 (28.7318, 49.8059)
  point P21 (44.6118, 49.8059)
  midpoint L14 P20
  midpoint L4 P21
  dimension "d247" diameter C1 = 1.7 (= "filament_hole_width")
  dimension "d250" diameter C2 = 1.7 (= "filament_hole_width")
extrude "Extrude12" cut sketch "Sketch9" profile of L4 L14 C1 C2 no distance stored
sketch "Sketch16" plane through (0, 19.6118, 0) normal (0, -1, 0) x axis (1, 0, 0)
  dimension "d253" = 3
extrude "Extrude22" cut sketch "Sketch16" against normal blind 2
extrude "Extrude23" cut sketch "Sketch15" profile of L7 C1 against normal blind 260 and along normal blind 80
sketch "Sketch17" plane through (0, 19.6118, 0) normal (0, -1, 0) x axis (1, 0, 0)
  dimension "d258" = 3
extrude "Extrude24" cut sketch "Sketch17" against normal blind 2
extrude "Extrude26" cut sketch "Text" against normal blind 2
extrude "Extrude27" cut sketch "Text" against normal blind 2
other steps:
create_component "CreateComponent1"
create_component "CreateComponent2"
create_component "CreateComponent3"
create_component "CreateComponent4"
named bodies: "Wall anchor part", "Base plate with slot", "Wall anchor part (1)", "Wall anchor part (2)", "Wall anchor part (3)"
